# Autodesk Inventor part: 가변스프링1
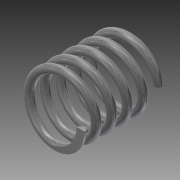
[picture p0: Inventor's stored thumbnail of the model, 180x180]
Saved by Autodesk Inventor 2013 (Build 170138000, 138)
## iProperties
Created: 2015-02
Part Number: 가변스프링1
Material: 강철, 탄소
Document SubType Name: Modeling
Designer: WINDOWS7
Mass: 18.7747 g
Surface Area: 32.4435 cm^2
Volume: 2.3856 cm^3
Density: 7.87 g/cm^3
Author: WINDOWS7
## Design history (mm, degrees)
sketch "스케치1"
  geometry: L1 (0, 0)-(11, 0); L2 (11, 0)-(11, 29.043); L3 (11, 29.043)-(0, 29.043); L4 (0, 29.043)-(0, 0); C1 r 1.5 at (11, 0)
  constraints: 8 end point, 2 parallel, 1 centre point, 1 coincident, 1 horizontal, 1 perpendicular
  dimensions: "d0" = 29.04259 distance of L3.end L1.start (derived); "d2" = 22 diameter of L2 L4; "d3" = 3 diameter of C1
feature "코일1" sketch "스케치1" pitch "d4" = 10; turns "d6" = 5; dims "d5" = 29.04259 (= d0), "d7" = 0, angle "d8" = 90 deg, angle "d9" = 90 deg, "d10" = 0, "d11" = 0
feature "분할1"
node "작업 평면1"
feature "분할2"
node "솔리드1"
other parameters: "d12" = 90 deg
